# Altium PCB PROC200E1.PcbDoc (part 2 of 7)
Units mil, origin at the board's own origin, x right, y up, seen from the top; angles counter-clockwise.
Board outline 4163.97 x 3505.34 mil, 6 copper layers (Top Layer, GND1, SIG1, PWR, GND2, Bottom), stack 58.132 mil thick; 367 components, 387 nets, 1784 pads, 858 vias.
Unrouted connection lines stored in the file: 17.
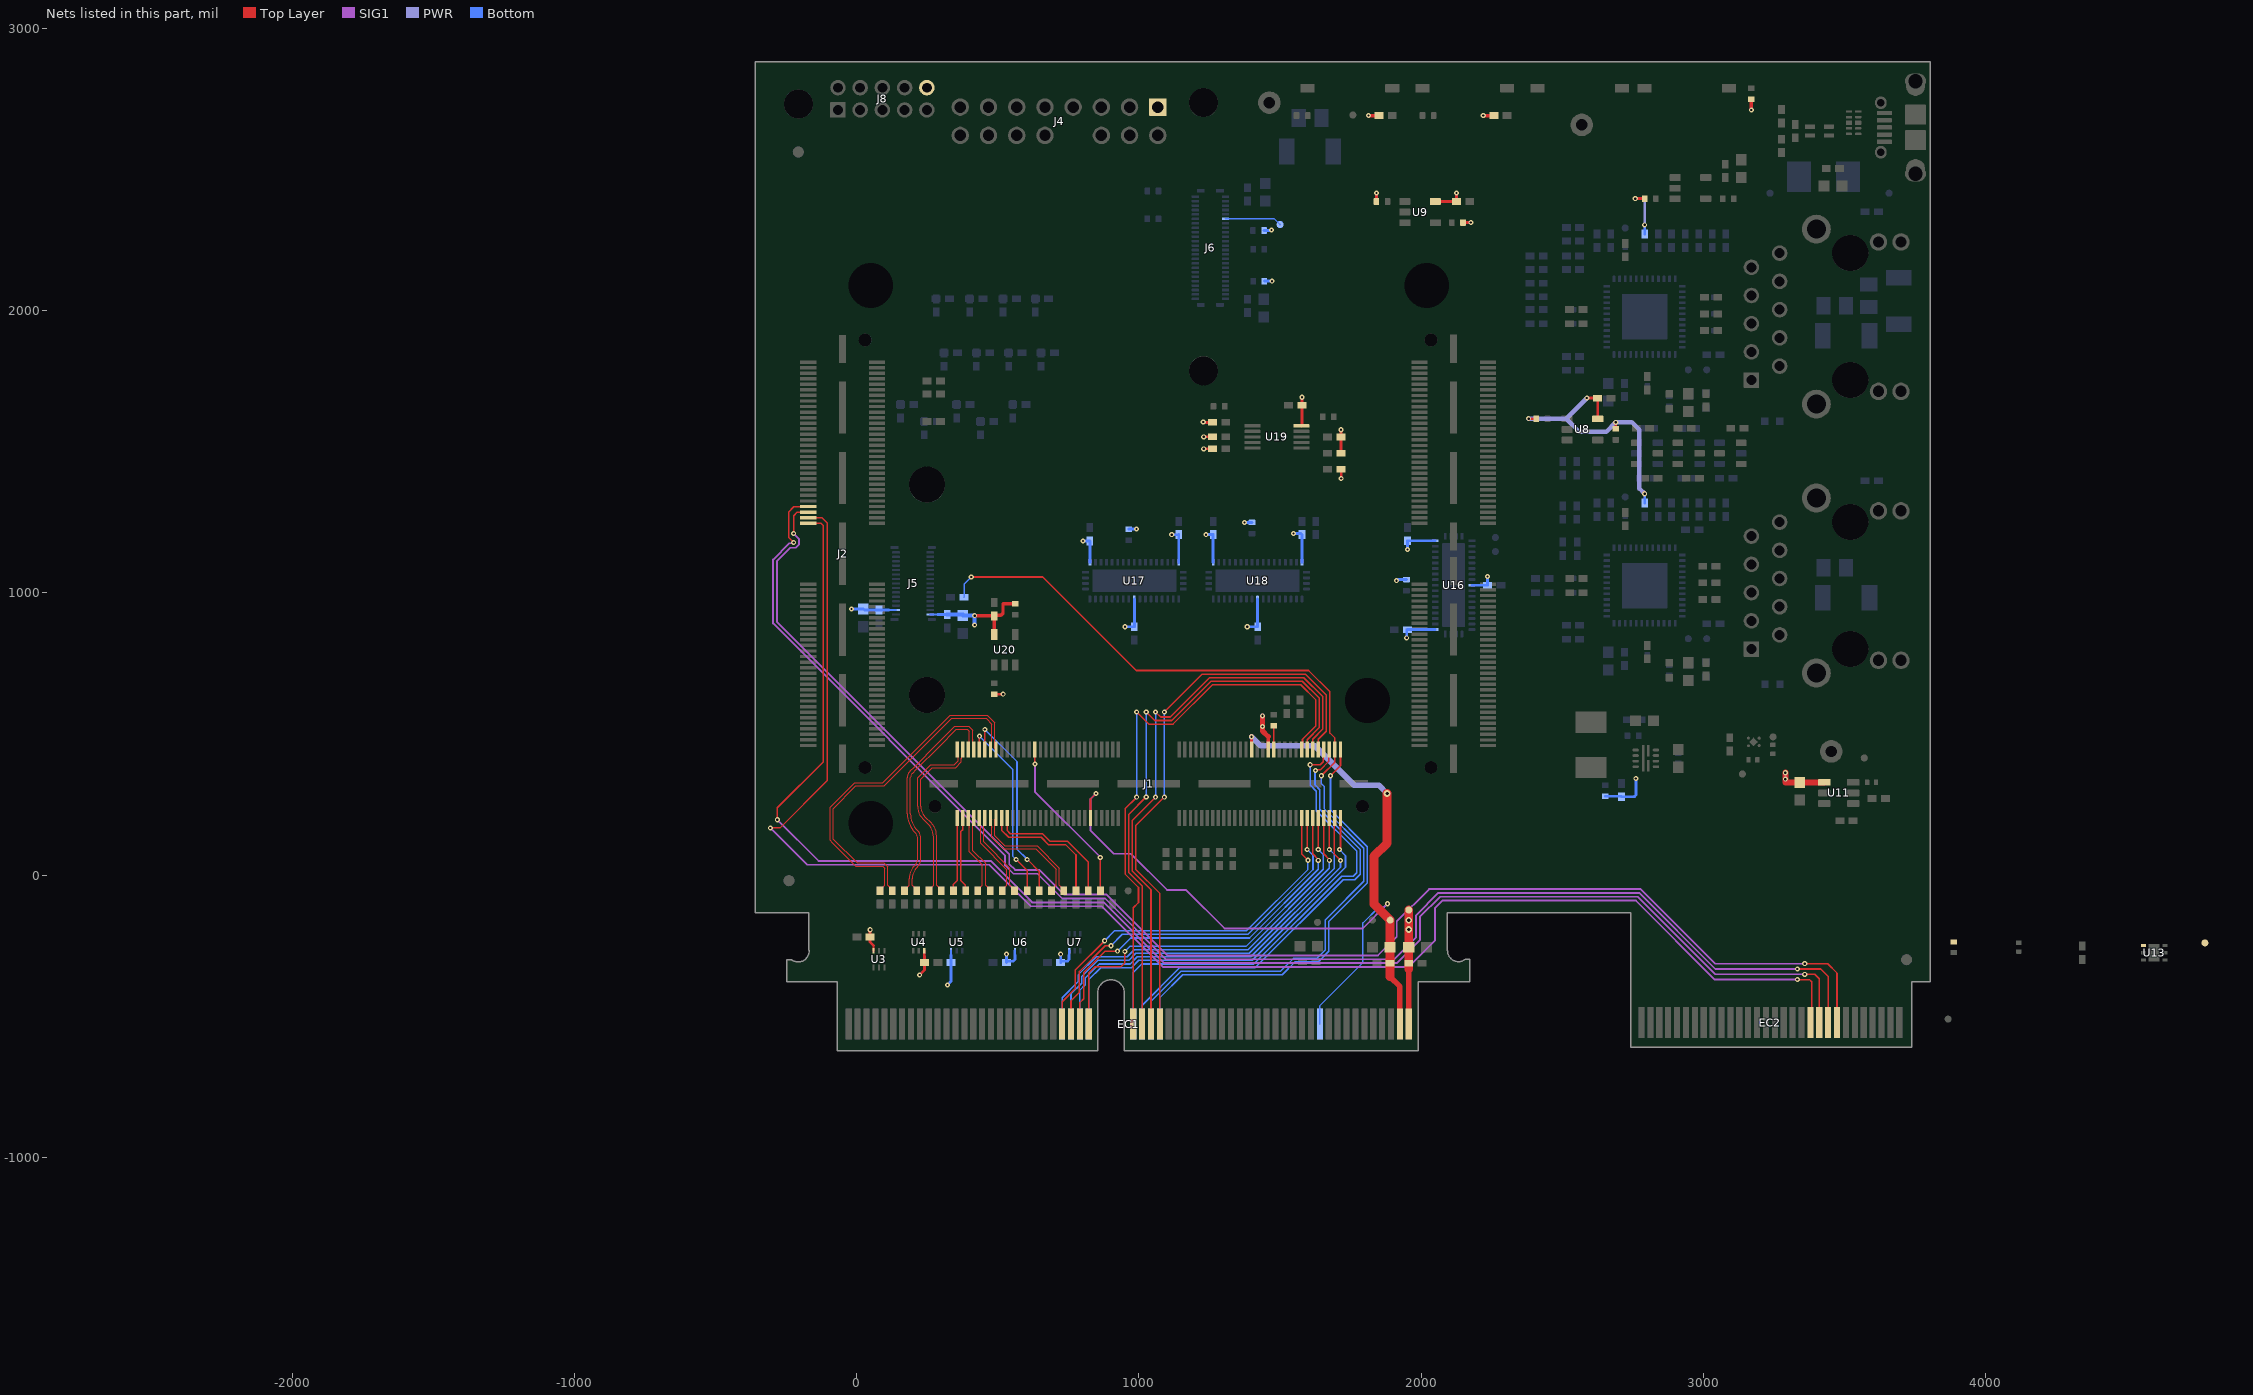
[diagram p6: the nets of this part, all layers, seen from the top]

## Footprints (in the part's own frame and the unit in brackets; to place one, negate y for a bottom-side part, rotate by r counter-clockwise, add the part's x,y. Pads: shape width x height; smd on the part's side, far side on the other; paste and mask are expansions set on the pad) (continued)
DBV0006A-MFG [mm]
  rrect17% 1.1x0.6 smd paste+0 mask+0: 1(-1.3,0.95) 2(-1.3,0) 3(-1.3,-0.95) 4(1.3,-0.95) 5(1.3,0) 6(1.3,0.95)
  silkscreen extent -2.52,-1.53 0.35,1.53, body extent -1.4,-1.45 1.4,1.45, height 1.45
DGS0010A-MFG [mm]
  rrect33% 1.45x0.3 smd paste+0 mask+0: 1(-2.2,1) 2(-2.2,0.5) 3(-2.2,0) 4(-2.2,-0.5) 5(-2.2,-1) 6(2.2,-1) 7(2.2,-0.5) 8(2.2,0) 9(2.2,0.5) 10(2.2,1)
  silkscreen extent -3.6,-1.55 1.05,1.55, body extent -3.03,-1.8 3.03,1.8, height 0.25
DPK0006A [mm] "SON, 6-Leads, Body 1.6x1.6mm, Pitch 0.5mm, TI Recommended"
  rect 0.5x0.2 smd paste+0: 1(-0.75,0.5) 2(-0.75,0) 3(-0.75,-0.5) 4(0.75,-0.5) 5(0.75,0) 6(0.75,0.5)
  Top Layer region: -0.65,0.5 -0.5,0.5 -0.5,0.7 -0.65,0.7
  silkscreen extent -0.97,-1 0.85,1, body extent -0.85,-0.85 0.85,0.85, height 0.61
DQA0010A [mm] "SON, 10-Leads, Body 1x2.5mm, Pitch 0.5mm, TI Recommended"
  rrect50% 0.565x0.2 smd: 1(-0.417,1) 2(-0.417,0.5) 4(-0.417,-0.5) 5(-0.417,-1) 6(0.417,-1) 7(0.417,-0.5) 9(0.417,0.5) 10(0.417,1)
  rrect28% 0.565x0.36 on Top Paste: 3(-0.417,0) 8(0.417,0)
  rrect25% 0.565x0.4 smd paste-0.2: 3(-0.417,0) 8(0.417,0)
  silkscreen extent -0.67,-1.45 0.55,1.45, body extent -0.55,-1.3 0.55,1.3, height 0.56
DQN0004A-MFG [mm]
  round 0.279 smd paste-1000 mask-1000: 1(-0.505,0.33) 2(-0.505,-0.33)
  round 0.251 smd paste-1000 mask-1000: 3(0.459,-0.346) 4(0.459,0.346)
  rrect17% 0.58x0.58 smd rot 135 paste-1000 mask-1000: 5(0,0)
  Top Layer region: -0.66,-0.485 -0.2,-0.485 -0.2,-0.385 -0.41,-0.175 -0.66,-0.175
  Top Layer region: 0.66,0.485 0.2,0.485 0.2,0.385 0.41,0.175 0.66,0.175
  Top Layer region: 0.66,-0.485 0.2,-0.485 0.2,-0.385 0.41,-0.175 0.66,-0.175
  Top Layer region: -0.66,0.485 -0.2,0.485 -0.2,0.385 -0.41,0.175 -0.66,0.175
  silkscreen extent -1.35,-0.9 0.53,0.9, body extent -0.5,-0.5 0.5,0.5, height 0.4
DRV0006A [mm] "SON, 6-Leads, Body 2x2mm, Pitch 0.65mm, Thermal Pad 1.6x1mm, TI Recommended"
  rrect33% 0.45x0.3 smd: 1(-0.975,0.65) 2(-0.975,0) 3(-0.975,-0.65) 4(0.975,-0.65) 5(0.975,0) 6(0.975,0.65)
  rrect14% 1x0.7 on Top Paste: 7(0,-0.45) 7(0,0.45)
  rrect10% 1x1.6 smd paste-0.5: 7(0,0)
  silkscreen extent -1.05,-1.2 1.05,1.2, body extent -1.05,-1.05 1.05,1.05, height 0.81
FCC_disclaimer [mil]
Fiducial10-20 [mm]
  round 1 smd mask+0.5: 1(0,0)
  Top Layer keep-out circle w1.178: c0,0 r0.5
FP-629105150921_CONN_PTH_USB_8MM0_5MM6-MFG [mm]
  rrect25% 0.4x1.35 smd paste+0 mask+0: 1(-1.3,2.335) 2(-0.65,2.335) 3(0,2.335) 4(0.65,2.335) 5(1.3,2.335)
  rrect100% 1.15x1.05 hole 0.65 slot 0.75 at 0 deg paste-2539.97 mask+0: 6(-2.225,2.65) 7(2.225,2.65)
  rrect100% 1.35x1.9 hole 1.3 slot 0.75 at 0 deg paste-2539.97 mask+0: 8(-4.175,-0.47) 11(4.173,-0.47)
  round 1.71 smd paste+0 mask+0: 8(-3.699,-0.47) 11(3.699,-0.47)
  rrect6% 1.8x1.9 smd paste+0 mask+0: 9(-1.15,-0.47) 10(1.15,-0.47)
  Top Layer region: 2.6,0.48 4.35,0.48 4.541,0.442 4.704,0.334 4.812,0.171 4.85,-0.02 4.85,-0.02 4.85,-0.92 4.812,-1.111 4.704,-1.274 4.541,-1.382 4.35,-1.42 4.35,-1.42 2.6,-1.42
  Top Layer region: -2.6,-1.42 -4.35,-1.42 -4.541,-1.382 -4.704,-1.274 -4.812,-1.111 -4.85,-0.92 -4.85,-0.92 -4.85,-0.02 -4.812,0.171 -4.704,0.334 -4.541,0.442 -4.35,0.48 -4.35,0.48 -2.6,0.48
  silkscreen extent -3.8,0.86 3.8,3.71, body extent -4.95,-2.7 4.95,3.27, height 0.25
FP-BLM18EG101TN1D_0603-MFG [mm]
  rrect15% 0.65x0.7 smd paste+0 mask+0: 1(-0.675,0) 2(0.675,0)
  silkscreen extent -0.87,-0.75 0.87,0.75, body extent -0.8,-0.4 0.8,0.4, height 0.65
FP-BSS138LT1G_SOT-23-3-MFG [mm]
  rrect18% 0.95x0.56 smd paste+0 mask+0: 1(-0.975,0.95) 2(-0.975,-0.95) 3(0.975,0)
  silkscreen extent -2.15,-1.52 0.7,1.52, body extent -1.2,-1.45 1.2,1.45, height 1.11
FP-DF40GB(1.5)-30DS-0.4V(58)_HDR30-MFG [mm]
  rrect50% 0.2x0.7 smd paste-1000 mask+0: 1(-2.8,-1.54) 2(-2.8,1.54) 3(-2.4,-1.54) 4(-2.4,1.54) 5(-2,-1.54) 6(-2,1.54) 7(-1.6,-1.54) 8(-1.6,1.54) 9(-1.2,-1.54) 10(-1.2,1.54) 11(-0.8,-1.54) 12(-0.8,1.54) 13(-0.4,-1.54) 14(-0.4,1.54) 15(0,-1.54) 16(0,1.54) 17(0.4,-1.54) 18(0.4,1.54) 19(0.8,-1.54) 20(0.8,1.54) 21(1.2,-1.54) 22(1.2,1.54) 23(1.6,-1.54) 24(1.6,1.54) 25(2,-1.54) 26(2,1.54) 27(2.4,-1.54) 28(2.4,1.54) 29(2.8,-1.54) 30(2.8,1.54)
  rrect36% 0.28x0.72 smd paste-1000 mask+0: 31(-3.24,1.68) 32(3.24,1.68) 33(-3.24,-1.68) 34(3.24,-1.68)
  silkscreen extent -4.47,-2.56 4.47,1.84, body extent -4.32,-1.84 4.32,1.84, height 1.6
FP-DF40GB-48DP-0.4V(58)_HDR48-MFG [mm]
  rrect43% 0.23x0.66 smd paste-1000 mask+0: 1(-4.6,-1.355) 2(-4.6,1.355) 3(-4.2,-1.355) 4(-4.2,1.355) 5(-3.8,-1.355) 6(-3.8,1.355) 7(-3.4,-1.355) 8(-3.4,1.355) 9(-3,-1.355) 10(-3,1.355) 11(-2.6,-1.355) 12(-2.6,1.355) 13(-2.2,-1.355) 14(-2.2,1.355) 15(-1.8,-1.355) 16(-1.8,1.355) 17(-1.4,-1.355) 18(-1.4,1.355) 19(-1,-1.355) 20(-1,1.355) 21(-0.6,-1.355) 22(-0.6,1.355) 23(-0.2,-1.355) 24(-0.2,1.355) 25(0.2,-1.355) 26(0.2,1.355) 27(0.6,-1.355) 28(0.6,1.355) 29(1,-1.355) 30(1,1.355) 31(1.4,-1.355) 32(1.4,1.355) 33(1.8,-1.355) 34(1.8,1.355) 35(2.2,-1.355) 36(2.2,1.355) 37(2.6,-1.355) 38(2.6,1.355) 39(3,-1.355) 40(3,1.355) 41(3.4,-1.355) 42(3.4,1.355) 43(3.8,-1.355) 44(3.8,1.355) 45(4.2,-1.355) 46(4.2,1.355) 47(4.6,-1.355) 48(4.6,1.355)
  rrect29% 0.35x0.7 smd paste-1000 mask+0: 49(-5.135,0.86) 50(5.135,0.86) 51(-5.135,-0.86) 52(5.135,-0.86)
  Top Layer keep-out region: 6.17,1.685 4.86,1.685 4.86,0.94 5.46,0.94 5.46,-0.94 4.86,-0.94 4.86,-1.685 6.17,-1.685
  Top Layer keep-out region: -6.17,1.685 -4.86,1.685 -4.86,0.94 -5.46,0.94 -5.46,-0.94 -4.86,-0.94 -4.86,-1.685 -6.17,-1.685
  silkscreen extent -5.53,-2.37 5.53,0.14, body extent -5.38,-1.49 5.38,1.49, height 1.29
FP-GRM155C81E105KE11D_0402-MFG [mm]
  rrect25% 0.4x0.5 smd paste+0 mask+0: 1(-0.4,0) 2(0.4,0)
  silkscreen extent -0.53,-0.65 0.53,0.65, body extent -0.5,-0.25 0.5,0.25, height 0.6
"FP-GRM155R61E225KE11D_0402 (1005 metric)-MFG" [mm]
  rrect22% 0.45x0.6 smd paste+0 mask+0: 1(-0.475,0) 2(0.475,0)
  silkscreen extent -0.6,-0.64 0.6,0.65, body extent -0.8,-0.45 0.8,0.45, height 0.25
FP-LPJG16314A4NL_CONN_RJ45-MFG [mm]
  rrect7% 1.4x1.4 hole 0.9 paste-2539.97 mask+0: 1(-5.715,9.015)
  round 1.4 hole 0.9 paste-2539.97 mask+0: 2(-4.445,6.475) 3(-3.175,9.015) 4(-1.905,6.475) 5(-0.635,9.015) 6(0.635,6.475) 7(1.905,9.015) 8(3.175,6.475) 9(4.445,9.015) 10(5.715,6.475)
  round 1.57 hole 1.02 paste-2539.97 mask+0: 11(6.725,-2.415) 12(6.725,-4.445) 13(-6.725,-2.415) 14(-6.725,-4.445)
  round 2.6 hole 1.7 paste-2539.97 mask+0: 15(-7.875,3.175) 16(7.875,3.175)
  round 3.25 hole 3.25 unplated paste-2539.97 mask+0: ""(-5.715,0.125) ""(5.715,0.125)
  silkscreen extent -9.65,-10.75 8.1,10.75, body extent -9.28,-10.85 9.28,10.85, height 0.25
FP-RC0402JR-0710KL_0402-MFG [mm]
  rrect20% 0.5x0.6 smd paste+0 mask+0: 1(-0.5,0) 2(0.5,0)
  silkscreen extent -0.5,-0.67 0.5,0.67, body extent -0.85,-0.4 0.85,0.4, height 0.25
FP-TDA01H0SB1R_SMT_SW_2MM40_6MM20-MFG [mm]
  rrect13% 1.27x0.76 smd paste+0 mask+0: 1(-3.81,0) 2(3.81,0)
  silkscreen extent -5.12,-1.2 3.1,1.2, body extent -4.54,-1.3 4.54,1.3, height 0.25
FP-TMM-105-01-T-D_HDR10-MFG [mm]
  rrect7% 1.39x1.39 hole 0.89 paste-2539.97 mask+0: 1(-4,-1)
  round 1.39 hole 0.89 paste-2539.97 mask+0: 2(-4,1) 3(-2,-1) 4(-2,1) 5(0,-1) 6(0,1) 7(2,-1) 8(2,1) 9(4,-1) 10(4,1)
  body extent -5,-1.97 5,1.97, height 4.88
FP-TSW-108-08-G-D-RA-008_HDR15-MFG [mm]
  rrect6% 1.57x1.57 hole 1.02 paste-2539.97 mask+0: 1(8.89,-2.77)
  round 1.57 hole 1.02 paste-2539.97 mask+0: 2(8.89,-5.31) 3(6.35,-2.77) 4(6.35,-5.31) 5(3.81,-2.77) 6(3.81,-5.31) 7(1.27,-2.77) 9(-1.27,-2.77) 10(-1.27,-5.31) 11(-3.81,-2.77) 12(-3.81,-5.31) 13(-6.35,-2.77) 14(-6.35,-5.31) 15(-8.89,-2.77) 16(-8.89,-5.31)
  silkscreen extent -10.35,-2.89 10.35,1.34, body extent -10.16,-5.65 10.16,7.11, height 5.69
IHLP-2020BZ [mm] "Vishay Dale recommended land pattern.  Document 34261 rev 12-Sept-13"
  rect 1.915x2.79 smd: 1(-2.037,0) 2(2.037,0)
  silkscreen extent -2.9,-2.7 2.9,2.7, body extent -2.87,-2.72 2.87,2.72, height 2
IND_DLW21S [mm] "muRata"
  rrect25% 0.4x0.9 smd: 1(-0.4,0.85) 2(-0.4,-0.85) 3(0.4,-0.85) 4(0.4,0.85)
  silkscreen extent -1.23,0.66 -0.98,0.92, body extent -0.6,-1 0.6,1, height 1.21
Keystone5002 [mil] "For Keystone 500x miniature loop terminals"
  round 80 hole 40: 1(0,0)
  silkscreen extent -52,-52 52,52, body extent -49,-49 49,49, height 182
Label_650x200 [mil] "Thermal Transfer Label"
  round 1 on Mech13: 0(0,0)
  silkscreen extent -325,-100 325,100, body extent -325,-100 325,100, height 1
MTG_159mil [mil] "159mil Non Plated Hole"
  round 150 hole 159 unplated: 1(0,0)
RGZ0048B-MFG [mm]
  rrect42% 0.6x0.24 smd paste+0 mask+0: 1(-3.4,2.75) 2(-3.4,2.25) 3(-3.4,1.75) 4(-3.4,1.25) 5(-3.4,0.75) 6(-3.4,0.25) 7(-3.4,-0.25) 8(-3.4,-0.75) 9(-3.4,-1.25) 10(-3.4,-1.75) 11(-3.4,-2.25) 12(-3.4,-2.75) 25(3.4,-2.75) 26(3.4,-2.25) 27(3.4,-1.75) 28(3.4,-1.25) 29(3.4,-0.75) 30(3.4,-0.25) 31(3.4,0.25) 32(3.4,0.75) 33(3.4,1.25) 34(3.4,1.75) 35(3.4,2.25) 36(3.4,2.75)
  rrect42% 0.24x0.6 smd paste+0 mask+0: 13(-2.75,-3.4) 14(-2.25,-3.4) 15(-1.75,-3.4) 16(-1.25,-3.4) 17(-0.75,-3.4) 18(-0.25,-3.4) 19(0.25,-3.4) 20(0.75,-3.4) 21(1.25,-3.4) 22(1.75,-3.4) 23(2.25,-3.4) 24(2.75,-3.4) 37(2.75,3.4) 38(2.25,3.4) 39(1.75,3.4) 40(1.25,3.4) 41(0.75,3.4) 42(0.25,3.4) 43(-0.25,3.4) 44(-0.75,3.4) 45(-1.25,3.4) 46(-1.75,3.4) 47(-2.25,3.4) 48(-2.75,3.4)
  rrect2% 4.1x4.1 smd paste-1000 mask+0: 49(0,0)
  silkscreen extent -4.38,-3.57 3.57,3.57, body extent -3.5,-3.5 3.5,3.5, height 1.02
RUA0042A-MFG [mm]
  rrect40% 0.6x0.25 smd paste+0 mask+0: 1(-1.65,4) 2(-1.65,3.5) 3(-1.65,3) 4(-1.65,2.5) 5(-1.65,2) 6(-1.65,1.5) 7(-1.65,1) 8(-1.65,0.5) 9(-1.65,0) 10(-1.65,-0.5) 11(-1.65,-1) 12(-1.65,-1.5) 13(-1.65,-2) 14(-1.65,-2.5) 15(-1.65,-3) 16(-1.65,-3.5) 17(-1.65,-4) 22(1.65,-4) 23(1.65,-3.5) 24(1.65,-3) 25(1.65,-2.5) 26(1.65,-2) 27(1.65,-1.5) 28(1.65,-1) 29(1.65,-0.5) 30(1.65,0) 31(1.65,0.5) 32(1.65,1) 33(1.65,1.5) 34(1.65,2) 35(1.65,2.5) 36(1.65,3) 37(1.65,3.5) 38(1.65,4)
  rrect40% 0.25x0.6 smd paste+0 mask+0: 18(-0.75,-4.4) 19(-0.25,-4.4) 20(0.25,-4.4) 21(0.75,-4.4) 39(0.75,4.4) 40(0.25,4.4) 41(-0.25,4.4) 42(-0.75,4.4)
  rrect5% 2.05x7.55 smd paste-1000 mask+0: 43(0,0)
  silkscreen extent -2.65,-4.55 1.8,4.55, body extent -1.75,-4.5 1.75,4.5, height 0.8
RWK0011B [mm] "QFN, 11-Leads, Body 2.1x2.1mm, Pitch 0.5mm, TI Recommended"
  rect 1.05x0.2 smd paste-0.1: 1(-0.675,0.225) 7(0.675,0.225)
  rect 2.4x0.2 smd paste-0.1: 2(0,-0.225)
  oval 0.25x0.575 smd: 3(-0.75,-0.913) 4(-0.25,-0.913) 5(0.25,-0.913) 6(0.75,-0.913) 8(0.75,0.913) 9(0.25,0.913) 10(-0.25,0.913) 11(-0.75,0.913)
  silkscreen extent -1.2,-0.93 1.2,1.1, body extent -1.05,-1.05 1.05,1.05, height 1.01
SAMTEC_QTH-060-01-L-D-A [mm] "SMD, 60x2 Position, Body 40.01x5.97mm"
  rect 0.305x1.45 smd: 1(-17.25,3.086) 2(-17.25,-3.086) 3(-16.75,3.086) 4(-16.75,-3.086) 5(-16.25,3.086) 6(-16.25,-3.086) 7(-15.75,3.086) 8(-15.75,-3.086) 9(-15.25,3.086) 10(-15.25,-3.086) 11(-14.75,3.086) 12(-14.75,-3.086) 13(-14.25,3.086) 14(-14.25,-3.086) 15(-13.75,3.086) 16(-13.75,-3.086) 17(-13.25,3.086) 18(-13.25,-3.086) 19(-12.75,3.086) 20(-12.75,-3.086) 21(-12.25,3.086) 22(-12.25,-3.086) 23(-11.75,3.086) 24(-11.75,-3.086) 25(-11.25,3.086) 26(-11.25,-3.086) 27(-10.75,3.086) 28(-10.75,-3.086) 29(-10.25,3.086) 30(-10.25,-3.086) 31(-9.75,3.086) 32(-9.75,-3.086) 33(-9.25,3.086) 34(-9.25,-3.086) 35(-8.75,3.086) 36(-8.75,-3.086) 37(-8.25,3.086) 38(-8.25,-3.086) 39(-7.75,3.086) 40(-7.75,-3.086) 41(-7.25,3.086) 42(-7.25,-3.086) 43(-6.75,3.086) 44(-6.75,-3.086) 45(-6.25,3.086) 46(-6.25,-3.086) 47(-5.75,3.086) 48(-5.75,-3.086) 49(-5.25,3.086) 50(-5.25,-3.086) 51(-4.75,3.086) 52(-4.75,-3.086) 53(-4.25,3.086) 54(-4.25,-3.086) 55(-3.75,3.086) 56(-3.75,-3.086) 57(-3.25,3.086) 58(-3.25,-3.086) 59(-2.75,3.086) 60(-2.75,-3.086) 61(2.75,3.086) 62(2.75,-3.086) 63(3.25,3.086) 64(3.25,-3.086) 65(3.75,3.086) 66(3.75,-3.086) 67(4.25,3.086) 68(4.25,-3.086) 69(4.75,3.086) 70(4.75,-3.086) 71(5.25,3.086) 72(5.25,-3.086) 73(5.75,3.086) 74(5.75,-3.086) 75(6.25,3.086) 76(6.25,-3.086) 77(6.75,3.086) 78(6.75,-3.086) 79(7.25,3.086) 80(7.25,-3.086) 81(7.75,3.086) 82(7.75,-3.086) 83(8.25,3.086) 84(8.25,-3.086) 85(8.75,3.086) 86(8.75,-3.086) 87(9.25,3.086) 88(9.25,-3.086) 89(9.75,3.086) 90(9.75,-3.086) 91(10.25,3.086) 92(10.25,-3.086) 93(10.75,3.086) 94(10.75,-3.086) 95(11.25,3.086) 96(11.25,-3.086) 97(11.75,3.086) 98(11.75,-3.086) 99(12.25,3.086) 100(12.25,-3.086) 101(12.75,3.086) 102(12.75,-3.086) 103(13.25,3.086) 104(13.25,-3.086) 105(13.75,3.086) 106(13.75,-3.086) 107(14.25,3.086) 108(14.25,-3.086) 109(14.75,3.086) 110(14.75,-3.086) 111(15.25,3.086) 112(15.25,-3.086) 113(15.75,3.086) 114(15.75,-3.086) 115(16.25,3.086) 116(16.25,-3.086) 117(16.75,3.086) 118(16.75,-3.086) 119(17.25,3.086) 120(17.25,-3.086)
  rect 2.54x0.64 smd: A1(-18.44,0) A4(-1.55,0) A5(1.56,0) A8(18.45,0)
  rect 4.7x0.64 smd: A2(-13.17,0) A3(-6.82,0) A6(6.83,0) A7(13.18,0)
  round 1.15 hole 1.15 unplated mask+0: MH1(-19.24,2.03) MH2(19.24,2.03)
  silkscreen extent -20,-2.99 20,2.99, body extent -20.07,-3.56 19.94,3.56, height 4.32
SMB-Bi [mil] "Molded Diode, 2-Leads, Body 5.4x3.6mm, IPC Medium Density, based on OnSemi component dimensions"
  rect 85x107.99 smd: 1(-87.01,0) 2(87.01,0)
  silkscreen extent -125,-79 125,79, body extent -104,-73 104,73, height 89
TI_Stacked_Overlay_Small [mil]
  silkscreen extent -418,-98 418,98
TP_25MIL-SMT [mil]
  round 25 smd mask-2.5: 1(0,0)
WEEE_Minimum [mil] "WEEElie bin"
  silkscreen extent -95,-172 99,104

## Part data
C1 C9 C15 C21 C23 C25 C27 C29 C31 C45 C51 C57 C59 C72 C74 C102 C104: library part CMP-0086062-1, "CAP, CERM, 10 µF, 16 V,+/- 20%, X6S, 0603", Cap_Case=0603, Manufacturer=MuRata, TempCo=X6S, Tolerance_%=20%, Value2=16V, ValueDisplayed=10µF
C2 C10 C16 C38 C46 C52 C75 C77 C88: library part CMP-0006352-2, "CAP, CERM, 0.01 uF, 25 V, +/- 10%, X7R, 0402", Cap_Case=0402, Manufacturer=MuRata, Supplier Part Number 1=490-6043-2-ND, TempCo=X7R, Tolerance_%=10%, Value1=Unknown, Value2=25V, ValueDisplayed=0.01uF
C3 C5 C7 C12 C14 C18 C20 C22 C24 C26 C28 C30 C32 C33 C34 C35 C36 C37 C39 C41 C43 C48 C50 C54 C56 C58 C60 C71 C103 C105 C109 C110 C111 C112 C113 C114 C115 C116 C117 C118 C121: library part CMP-0006659-2, "CAP, CERM, 0.1 uF, 25 V, +/- 10%, X7R, 0402", Cap_Case=0402, Manufacturer=MuRata, Supplier Part Number 1=490-10698-1-ND, TempCo=X7R, Tolerance_%=10%, Value1=Unknown, Value2=25V, ValueDisplayed=0.1uF
C4 C6 C8 C11 C13 C17 C19 C40 C42 C44 C47 C49 C53 C55 C76 C78 C97 C100: library part CMP-0121658-2, "Chip Multilayer Ceramic Capacitors for General Purpose, 0402, 1.0uF, X6S, 22%, 10%, 25V", Manufacturer=Murata, Operating Temperature Range="-55°C to +105°C", TempCo=22%, Temperature Characteristic=X6S, Tolerance_%=10%, ValueDisplayed=1.0uF
C61 C108 C119 C120: library part CMP-0009436-2, "CAP, CERM, 1000 pF, 2000 V, +/- 10%, X7R, 1808", Cap_Case=1808, Manufacturer=MuRata, Supplier Part Number 1=490-8145-1-ND, TempCo=X7R, Tolerance_%=10%, Value1=Unknown, Value2=2000V, ValueDisplayed=1000pF
C62 C63 C64 C65 C66 C67 C68 C69 C70 C79 C80 C81 C82 C83 C84 C85 C86 C87 C94: library part CMP-0006456-2, "CAP, CERM, 330 pF, 50 V, +/- 5%, C0G/NP0, 0402", Cap_Case=0402, Manufacturer=MuRata, Supplier Part Number 1=490-1295-1-ND, TempCo=C0G/NP0, Tolerance_%=5%, Value1=Unknown, Value2=50V, ValueDisplayed=330pF
C73: library part CMP-0007306-5, "CAP, CERM, 22 uF, 6.3 V, +/- 20%, X5R, 0603", Cap_Case=0603, Manufacturer=MuRata, Supplier Part Number 1=490-7611-1-ND, TempCo=X5R, Tolerance_%=20%, Value1=Unknown, Value2=6.3V, ValueDisplayed=22uF
C89: library part CMP-0089929-1, "2.2µF ±10% 25V Ceramic Capacitor X5R 0402 (1005 Metric)", Digikey Part Number=490-12703-1-ND, Manufacturer=Murata, Mouser Part Number=81-GRM155R61E225KE1D, Operating Temperature Range="-55°C to +85°C", TempCo=15%, Temperature Characteristic=X5R, Tolerance_%=10%, ValueDisplayed=2.2uF, Voltage=25V
D1: library part CMP-0005599-2, "Diode, TVS, Bi, 6.5 V, SMB", Manufacturer=Littelfuse, Value1=600W
EC1: library part CMP-0003813-3, "C2000 controlCARD-120HSEC Edge Connector for Samtec HSEC8-160-01-L-DV-A-BL", Manufacturer=Any
EC2: library part CMP-0081961-1, "C2000 controlCARD-180HSEC (60-pin addon) Edge connector for Samtec HSEC8-130-01-L-DV-A", Manufacturer=Any
FB1 FB2 FB3 FB4 FB5 FB6: library part CMP-0122093-1, "Chip Ferrite Bead, 0603, 100Ω @ 100MHz, 25%, 0.045Ω, 2A", Impedance At Frequency="100Ω @ 100MHz", Manufacturer=Murata, Operating Temperature Range="-55°C to +125℃", Test Frequency=100MHz, Tolerance_%=25%
FID1 FID2 FID3 FID4 FID5 FID6: library part CMP-0077181-1, "Fiducial mark.  There is nothing to buy or mount.", Manufacturer=N/A
J1 J2 J3: library part CMP-0056023-2, "Socket, 0.5MM, 60x2, Gold, SMT", Manufacturer=Samtec, Supplier Part Number 1=SAM8189-ND
J4: library part CMP-0121702-1, "Connector Header Through Hole, Right Angle 16 position 0.100\" (2.54mm)", Digikey Part Number=612-TSW-108-08-G-D-RA-008-ND, Manufacturer=Samtec, Mouser Part Number=200-TSW10808GDRA008, Operating Temperature Range="-55°C to +125°C"
J5: library part CMP-0121593-1, "30 Position Connector Receptacle, Center Strip Contacts Surface Mount Gold", Current_A=300mA, Digikey Part Number=H124958CT-ND, Manufacturer=Hirose, Mouser Part Number=798-DF40GB1530DS4V58, Operating Temperature Range="-55°C to +85°C", Voltage_V=50V
J6: library part CMP-0121592-1, "48 Position Connector Plug, Outer Shroud Contacts Surface Mount Gold", Current_A=300mA, Digikey Part Number=H124956CT-ND, Manufacturer=Hirose, Mouser Part Number=798-DF40GB48DP04V58, Operating Temperature Range="-55°C to +85°C", Voltage_V=50V
J7: library part CMP-0097752-1, "Conn Micro USB 2.0 Type AB RCP 5 POS 0.65mm Solder RA SMD 5 Terminal 1 Port T/R", Current_A=1A, Digikey Part Number=732-5961-1-ND, Manufacturer="Wurth Electronics", Mouser Part Number=710-629105150921, Operating Temperature Range="-40°C to +85°C", Voltage_V=30V
J8: library part CMP-0086568-1, "Board-To-Board Connector, TMM Series, 10 Contacts, Header, 2 mm, Through Hole, 2 Rows", Current_A=3.2A, Manufacturer=Samtec, Voltage_V=281V
J9 J10: library part CMP-0093483-1, "RJ45 Connector with 1000 Base-TX Inetgrated Magnetic", Manufacturer=Link-PP, Operating Temperature Range="0°C to +70°C"
L1: library part CMP-0076826-3, "Coupled inductor, 0.28 A, 0.41 ohm, SMD", Manufacturer=MuRata, Supplier Part Number 1=490-5134-1-ND
L2: library part CMP-0063289-1, "Inductor, Shielded Drum Core, Powdered Iron, 1 uH, 7 A, 0.0189 ohm, SMD", Manufacturer=Vishay-Dale, Supplier Part Number 1=541-1087-1-ND, Value1="0.0189 ohm", Value2=7A, ValueDisplayed=1uH
LBL1: library part CMP-0003625-1, "Thermal Transfer Printable Labels, 0.650\" W x 0.200\" H - 10,000 per roll", Manufacturer=Brady, Supplier Part Number 1=97C5133
Logo1: library part CMP-0074844-1
Logo2: library part CMP-0074838-1, "Texas Instrument Corporate Signature"
Logo3: library part CMP-0074847-1, "FCC_disclaimer"
Logo4: library part CMP-0074769-3, Manufacturer="Texas Instruments"
MH1 MH2 MH3 MH4: library part CMP-0078424-2, "PCB Mounting Hole, No Pad", Manufacturer=Any, PartNumber=N/A
Q1 Q2 Q3 Q4 Q5 Q6: library part CMP-0122033-1, "N-Channel 50 V 200mA (Ta) 225mW (Ta) Surface Mount SOT-23-3 (TO-236)D3-3", Digikey Part Number=BSS138LT1GOSCT-ND, Drain To Source Breakdown Voltage=50V, Input Capacitace At Vds="40pF @ 25V", Manufacturer="On Semiconductor", Mouser Part Number=863-BSS138LT1G, Operating Temperature Range="-55°C to +150°C", Power_W=225mW, Pulse Drain Current=800mA
R1 R3 R4 R24 R25 R26 R27 R28 R29 R30 R31 R32 R33 R34 R35 R36 R37 R38 R39 R40 R41 R45 R46 R47 R48 R49 R50 R51 R52 R53 R54 R55 R56 R57 R59 R85 R87 R90 R92 R93 R109 R111 R113 R116 R119 R120 R125 R126 R127 R132 R134 R135 R136 R137 R138 R139 R140 R141 R142 R143 R144 R145 R146 R147 R148 R149 R150 R151 R152 R153 R156 R157 R158 R159 R160 R161 R162: library part CMP-0026992-3, "RES, 0, 5%, 0.1 W, AEC-Q200 Grade 0, 0402", Manufacturer=Panasonic, Power_W=100mW, Supplier Part Number 1=P0.0JCT-ND, TempCo="600 ppm/C", Tolerance_%=5%, Value2=0.1W, Value_Code=0000, ValueDisplayed=0
R2 R58 R155: library part CMP-0025975-3, "RES, 11.0 k, 1%, 0.063 W, AEC-Q200 Grade 0, 0402", Manufacturer=Vishay-Dale, Power_W=63mW, Supplier Part Number 1=541-11.0KLCT-ND, TempCo="100 ppm/C", Tolerance_%=1%, Value2=0.063W, Value_Code=11k0, ValueDisplayed=11.0k
R5 R60 R100 R101 R102 R103 R104 R105: library part CMP-0026231-2, "RES, 2.20 k, 1%, 0.063 W, AEC-Q200 Grade 0, 0402", Manufacturer=Vishay-Dale, Power_W=63mW, Supplier Part Number 1=541-2.20KLCT-ND, TempCo="100 ppm/C", Tolerance_%=1%, Value2=0.063W, Value_Code=2k20, ValueDisplayed=2.20k
R6 R7 R8 R9 R10 R11 R12 R13 R14 R15 R16 R17 R18 R19 R20 R21 R22 R23 R61 R62 R63 R64 R65 R66 R67 R68 R69 R70 R71 R72 R73 R74 R75 R76 R77 R78: library part CMP-0026237-2, "RES, 2.49 k, 1%, 0.063 W, AEC-Q200 Grade 0, 0402", Manufacturer=Vishay-Dale, Power_W=63mW, Supplier Part Number 1=541-2.49KLCT-ND, TempCo="100 ppm/C", Tolerance_%=1%, Value2=0.063W, Value_Code=2k49, ValueDisplayed=2.49k
R42 R43 R44 R79 R80 R81 R82 R83 R86 R88 R89 R91 R95 R96 R97 R98 R99 R106 R107 R122 R123 R124 R128 R133: library part CMP-0094798-1, "Res Thick Film 0402 10K Ohm 5% 0.063W(1/16W) ±100ppm/C Pad SMD T/R", Digikey Part Number=311-10KJRCT-ND, Manufacturer=YAGEO, Mouser Part Number=603-RC0402JR-0710KL, Operating Temperature Range="-55°C to +155°C", Power_W=63mW, TempCo=100ppm/°C, Tolerance_%=5%
R84 R94 R114 R121: library part CMP-0020616-3, "RES, 0, 5%, 0.125 W, AEC-Q200 Grade 0, 0805", Manufacturer=Panasonic, Power_W=125mW, Supplier Part Number 1=P0.0ACT-ND, TempCo="600 ppm/C", Tolerance_%=5%, Value2=0.125W, Value_Code=0000, ValueDisplayed=0
R108 R110 R112 R115 R117 R118: library part CMP-0026878-3, "RES, 220, 5%, 0.063 W, AEC-Q200 Grade 0, 0402", Manufacturer=Vishay-Dale, Power_W=63mW, Supplier Part Number 1=541-220JCT-ND, TempCo="200 ppm/C", Tolerance_%=5%, Value2=0.063W, Value_Code=220R, ValueDisplayed=220
R129: library part CMP-0026938-5, "RES, 4.7 k, 5%, 0.063 W, AEC-Q200 Grade 0, 0402", Manufacturer=Vishay-Dale, Power_W=63mW, Supplier Part Number 1=541-4.7KJCT-ND, TempCo="200 ppm/C", Tolerance_%=5%, Value2=0.063W, Value_Code=4k70, ValueDisplayed=4.7k
R130 R131: library part CMP-0026657-1, "RES, 1.00 k, 1%, 0.1 W, 0402", Manufacturer=Panasonic, Power_W=100mW, Supplier Part Number 1=P1.00KLCT-ND, TempCo="100 ppm/C", Tolerance_%=1%, Value2=0.1W, Value_Code=1k00, ValueDisplayed=1.00k
R154: library part CMP-0026989-6, "RES, 9.1 k, 5%, 0.063 W, AEC-Q200 Grade 0, 0402", Manufacturer=Vishay-Dale, Power_W=63mW, Supplier Part Number 1=541-9.1KJCT-ND, TempCo="200 ppm/C", Tolerance_%=5%, Value2=0.063W, Value_Code=9k10, ValueDisplayed=9.1k
SW1 SW2 SW3 SW4: library part CMP-0122841-1, "Dip Switch SPST 1 Position Surface Mount Slide (Standard) Actuator 25mA 24VDC", Coil Resistance_ohm=100mΩ, Contact Current Rating=25mA, Digikey Part Number=CKN10538CT-ND, Manufacturer="C&K Components", Mouser Part Number=611-TDA01H0SB1R, Operating Temperature Range="-40°C to +85°C"
TP1 TP2 TP3 TP4 TP18 TP25: "TEST POINT.  No entry in BOM.", Manufacturer=N/A
TP5 TP6 TP7 TP8 TP9 TP10 TP11 TP12 TP13 TP14 TP15 TP16 TP17 TP20 TP21 TP24: library part CMP-0078143-3, "TEST POINT.  No entry in BOM.", Manufacturer=N/A
TP19 TP22 TP23: library part CMP-0055139-2, "Test Point, Miniature, White, TH", Color=White, Manufacturer="Keystone Electronics", Supplier Part Number 1=36-5002-ND
U1 U2: library part CMP-0091377-1, "1/1 Transceiver Ethernet 48-VQFN (7x7)", Digikey Part Number=296-53377-1-ND, Manufacturer="Texas Instruments", Max Supply Voltage=3.45V, Min Supply Voltage=990mV, Mouser Part Number=595-DP83869HMRGZT, Operating Temperature Range="-40°C to +125°C"
U3 U4 U5 U6 U7: library part CMP-0043110-1, "Low-Capacitance + / - 15-kV ESD Protection Array for High-Speed Data Interfaces, 4 Channels, -40 to +85 degC, 6-pin USON (DPK), Green (RoHS & no Sb/Br)", Breakdown Voltage(Min)(V)=11, IO Capacitance(Typ)(pF)=1.5, Manufacturer="Texas Instruments"
U8 U9 U20: library part CMP-0051264-2, "Single 2-Input Positive–AND Gate with Open Drain Output,  DBV0005A (SOT-23-5)", F @ Nom Voltage(Max)(Mhz)=75, Generic Part Number=SN74AHC1G09, ICC @ Nom Voltage(Max)(mA)=0.01, Manufacturer="Texas Instruments", Operating Temperature Range="-55 to 125 C", Rating=Catalog, tpd @ Nom Voltage(Max)(ns)=11,7.5, Voltage(Nom)(V)=3.3,5
U10: library part CMP-0074023-2, "2-A Step Down Converter with Selectable Switching Frequency in HotRod package, RWK0011B (VQFN-HR-11)", Alternate Manufacturer="Texas Instruments", Alternate PartNumber=TPS62097RWKT
U11: library part CMP-0122847-1, "5.5-V, 2-A, 52-mΩ load switch with adj. rise time and adj. output discharge", Digikey Part Number=296-46278-1-ND, Manufacturer="Texas Instruments", Max Supply Voltage=5.5V, Mouser Part Number=595-TPS22918DBVR, Nominal Supply Current=8.3-10.2uA, Operating Temperature Range="-40°C to +105°C"
U12: library part CMP-0122846-1, "LDO Regulator Pos 1.1V 0.5A 4-Pin X2SON EP T/R", Digikey Part Number=296-51784-1-ND, Dropout Voltage=550mV, Manufacturer="Texas Instruments", Max Supply Voltage=5.5V, Min Supply Voltage=2V, Mouser Part Number=595-TLV75511PDQNR, Nominal Supply Current=25uA, Operating Temperature Range="-40°C to +125°C", Output Voltage=1.1V
U13: library part CMP-0036330-5, "Single Output High PSRR LDO, 500 mA, Fixed 3.3 V Output, 2.7 to 6.5 V Input, with Low IQ, 6-pin SON (DRV), -40 to 125 degC, Green (RoHS & no Sb/Br)", Manufacturer="Texas Instruments"
U14: library part CMP-0074276-1, "Single, Current-Limited, Power-Distribution Switch, DBV0005A (SOT-23-5)", Alternate Manufacturer="Texas Instruments", Alternate PartNumber=TPS2051BDBVT
U15: library part CMP-0073612-3, "4-Channel ESD Protection Diode for USB Type-C and HDMI 2.0, DQA0010A (USON-10)", Alternate Manufacturer="Texas Instruments"
U16 U17 U18: library part CMP-0093539-2, "IC MUX/DEMUX DDR3 1:2 42WQFN", Digikey Part Number=296-28307-1-ND, Manufacturer="Texas Instruments", Max Supply Voltage=3.6V, Min Supply Voltage=3V, Mouser Part Number=595-TS3DDR3812RUAR, Nominal Supply Current=300uA, On State Resistance=8Ω, Operating Temperature Range="-40°C to +85°C"
U19: library part CMP-0122044-1, "ESD-Protected, Low Capacitance, 2-Channel, 2:1 Switch, With Powered-off Protection", Digikey Part Number=296-48347-1-ND, Manufacturer="Texas Instruments", Max Supply Voltage=4.3V, Min Supply Voltage=3V, Mouser Part Number=595-TMUX154EDGSR, Nominal Supply Current=1uA, On State Resistance=6Ω, Operating Temperature Range="-40°C to +85°C"
ZZ1: library part CMP-0003616-3
ZZ2: library part CMP-0077236-1
ZZ3: library part CMP-0077237-1
ZZ4: library part CMP-0077238-1

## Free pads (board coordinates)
  round 1.38 on Mech4: 1(-2738.83,-78.63) 1(-2738.83,-78.63) 1(-2738.83,-68.78) 1(-2738.83,-21.54) 1(-2738.83,-11.7) 1(-2738.83,-11.7) 1(-2703.39,-78.63) 1(-2703.39,-78.63) 1(-2703.39,-68.78) 1(-2703.39,-21.54) 1(-2703.39,-11.7) 1(-2703.39,-11.7) 1(-2602,-78.63) 1(-2602,-78.63) 1(-2602,-68.78) 1(-2602,-21.54) 1(-2602,-11.7) 1(-2602,-11.7) 1(-2566.56,-78.63) 1(-2566.56,-78.63) 1(-2566.56,-68.78) 1(-2566.56,-21.54) 1(-2566.56,-11.7) 1(-2566.56,-11.7) 1(-1656.99,1356.81) 1(-1656.99,1356.81) 1(-1656.99,1392.24) 1(-1656.99,1392.24) 1(-1647.14,1356.81) 1(-1647.14,1392.24) 1(-1599.9,1356.81) 1(-1599.9,1392.24) 1(-1590.06,1356.81) 1(-1590.06,1356.81) 1(-1590.06,1392.24) 1(-1590.06,1392.24) 1(-1532.26,-29.39) 1(-1532.26,-29.39) 1(-1532.26,6.04) 1(-1532.26,6.04) 1(-1531.74,-141.35) 1(-1531.74,-141.35) 1(-1531.74,-105.92) 1(-1531.74,-105.92) 1(-1522.41,-29.39) 1(-1522.41,6.04) 1(-1521.9,-141.35) 1(-1521.9,-105.92) 1(-1475.17,-29.39) 1(-1475.17,6.04) 1(-1474.65,-105.92) 1(-1474.65,-141.35) 1(-1465.33,-29.39) 1(-1465.33,-29.39) 1(-1465.33,6.04) 1(-1465.33,6.04) 1(-1464.81,-105.92) 1(-1464.81,-105.92) 1(-1464.81,-141.35) 1(-1464.81,-141.35) 1(-1416.07,1313.15) 1(-1416.07,1313.15) 1(-1416.07,1348.59) 1(-1416.07,1348.59) 1(-1406.23,1313.15) 1(-1406.23,1348.59) 1(-1358.98,1313.15) 1(-1358.98,1348.59) 1(-1349.14,1313.15) 1(-1349.14,1313.15) 1(-1349.14,1348.59) 1(-1349.14,1348.59) 1(-1267.81,1181.64) 1(-1267.81,1181.64) 1(-1267.81,1191.49) 1(-1267.81,1238.73) 1(-1267.81,1248.57) 1(-1267.81,1248.57) 1(-1232.38,1181.64) 1(-1232.38,1181.64) 1(-1232.38,1248.57) 1(-1232.38,1248.57) 1(-1232.38,1191.49) 1(-1232.38,1238.73)
  round 1.5 on Mech16: 1(-474.89,503.61)
  round 2.46 on Mech16: 1(-69.32,1342.99) 1(-59.47,1342.99)
  round 1.48 on Mech16: 1(-59.48,1399.48) 1(-59.48,1399.48) 1(-59.48,1504.6) 1(-59.48,1504.6)
  round 2.5 on Mech16: 1(104.06,1504.6) 1(104.06,1504.6)
  round 102.99 hole 102.99: HOLE1(1228.45,1786.73) HOLE2(1228.45,2736.73) HOLE3(-206.55,2731.73)
  round 127.95 hole 127.95: HOLE4(248.97,637.58) HOLE5(248.97,1383.25)

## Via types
v1: diameter 18, hole 8, Top Layer to Bottom, tented both sides, 729 vias
v2: diameter 19.68, hole 7.87, Top Layer to Bottom, 77 vias
v3: diameter 24, hole 12, Top Layer to Bottom, tented both sides, 52 vias

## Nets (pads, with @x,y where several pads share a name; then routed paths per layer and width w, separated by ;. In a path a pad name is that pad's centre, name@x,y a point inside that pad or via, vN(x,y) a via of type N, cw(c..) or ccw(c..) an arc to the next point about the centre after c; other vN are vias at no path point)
3V3_EMU_HDR: C89.2 J4.1 TP24.1 U13.1
3V3_LDO2: C21.2 C22.1 C23.2 C24.1 C27.2 C28.1 C32.1 C33.1 C34.1 C35.1 C36.1 C37.2 C71.2 C74.2 C109.1 C110.1 C111.1 C112.1 C113.1 C114.1 C115.1 C116.1 C117.1 C118.1 C121.2 EC1.119 J1.28 J5.2 J5.3 J8.10 R5.2 R43.1 R44.1 R60.2 R79.1 R80.1 R86.1 R87.1 R88.1 R91.1 R95.1 R96.1 R99.1 R100.2 R101.2 R102.2 R103.2 R104.2 R105.2 R122.1 R123.1 R124.1 R130.2 R131.2 R133.1 TP2.1 U3.6 U4.6 U5.6 U6.6 U7.6 U8.5 U9.5 U11.1 U16.1 U16.17 U16.30 U17.1 U17.17 U17.30 U18.1 U18.17 U18.30 U19.10 U20.5 | length 4966.9
  Top Layer w8: U3.6@59.32,-268.47 59.32,-249.19 ; 239.67,-286.87 U4.6@239.67,-267.59
  Top Layer w10: v1(47.62,-193.75) C32.1@47.62,-219.5 47.62,-237.5 59.32,-249.19 ; v1(223,-354) 240.2,-336.8 C33.1@240.2,-310.04 240.2,-287.41 ; R122.1@486.93,640.53 487.16,640.76 518.76,640.76 v1(519,641) ; v1(1227.84,1605.69) 1230.01,1605.69 1231.7,1603.99 R103.2@1260.22,1603.99 ; v1@1230.21,1553.49 1230.54,1553.16 1259.89,1553.16 R101.2@1260.22,1553.49 ; v1@1230.86,1510.19 R104.2@1260.22,1510.19 ; U19.10@1575.63,1591.65 1576.56,1591.65 1577.47,1592.55 C118.1@1577.47,1664.99 v1(1577.47,1693) ; R105.2@1715.71,1437.99 1716.64,1437.06 v1(1716.64,1405.18) ; R100.2@1715.71,1494.49 R102.2@1715.71,1552.28 v1(1715.71,1577.71) ; R86.1@1841.54,2386.55 v1(1841.54,2417) ; U9.5@2050.57,2386.55 C71.2@2125,2386.55 v1(2125,2417) ; R124.1@2148.28,2311.75 v1(2176,2311.75) ; v1(2381,1617) 2381.32,1616.69 2408.04,1616.69 R43.1@2408.35,1616.37 ; v1@2587.02,1689.98 C37.2@2625.11,1689.97 2625.62,1689.46 U8.5@2625.62,1616.37 ; R44.1@2689.49,1580.94 v1(2689.49,1604) ; v1(2758.51,2396.67) R88.1@2792.46,2396.67
  Top Layer w12: v1(418,918.99) C121.2@487.49,918.99 ; U20.5@487.49,852.66 C121.2@487.49,918.31 ; C121.2@493.3,920.18 511.28,920.18 518.31,927.21 518.31,959.85 519.77,961.31 561.98,961.31 R123.1@562.29,961.62 ; J1.28@1458.21,444.88 1458.21,490.35 ; v1(1813,2691) R131.2@1850.46,2691 ; v1(2220.02,2691) R130.2@2257.48,2691 ; v1(3170,2711.17) R91.1@3170,2748.63
  Top Layer w18: v1(1438.21,564.07) v1(1438.21,526.36) 1438.21,510.35 1458.21,490.35
  Top Layer w20: EC1.119@1956.16,-528.32 1956.16,-333.01
  Top Layer w22: v1(3290.4,362.4) v1(3290.4,339.84) 3290.4,328.4 C74.2@3341.94,328.4 U11.1@3428.29,328.4
  Top Layer w31.5: 1956.16,-333.01 C28.1@1956.16,-312.16 C27.2@1956.16,-256.16 v3(1956.16,-193) v3(1956.16,-159.78) TP2.1@1956.16,-123.78
  PWR w10: v1(2758.51,2396.67) 2786.09,2396.67 2791.95,2390.81 v1(2791.95,2303.89)
  PWR w16: v1(2381,1617) 2514,1617 ; v1(2587,1690) 2551,1654 2514,1617 ; v1(2791.95,1351.13) 2773.54,1369.54 2773.54,1577.46 2747,1604 v1(2689.49,1604) 2655.49,1570 2561,1570 2514,1617
  Bottom w7.89: 113.79,938.68 J5.3@139.23,938.68 ; J5.2@260.49,922.93 285.93,922.93
  Bottom w8: 334.47,-284.23 U5.6@334.47,-267.59 ; 560.44,-284.23 U6.6@560.44,-267.59 ; 752.72,-284.23 U7.6@752.72,-267.59
  Bottom w10: v1(-18.28,942.62) C21.2@23.23,942.62 27.17,938.68 C22.1@79.23,938.68 113.79,938.68 ; 285.93,922.93 C24.1@320.49,922.93 ; v1(321.39,-389.19) 334.47,-376.11 C36.1@334.47,-309.81 334.47,-284.23 ; v1(530.44,-280.4) C34.1@530.44,-309.7 535.07,-305.07 554.58,-305.07 560.44,-299.21 560.44,-284.23 ; v1(722.72,-280.4) C35.1@722.72,-309.7 727.35,-305.07 746.86,-305.07 752.72,-299.21 752.72,-284.23 ; v1(801.8,1183.7) 825.97,1183.7 C114.1@826.28,1184.02 U17.1@826.28,1108 ; v1(950.4,879.94) C113.1@983.76,879.94 U17.30@983.76,978.08 ; R96.1@964.08,1225.52 964.32,1225.76 990.76,1225.76 v1(991,1226) ; v1@1116.34,1206.14 1116.48,1206 1141.1,1206 C112.1@1141.24,1206.14 U17.17@1141.24,1108 ; v1@1238.18,1206.28 1238.32,1206.14 C117.1@1262.94,1206.14 ; U18.1@1262.94,1108 C117.1@1262.94,1206.14 ; C117.1@1263.09,1206.28 C117.1@1262.94,1206.14 ; v1@1373.89,1248.16 1374.53,1248.8 1400.1,1248.8 R99.1@1400.74,1249.45 ; v1(1383.81,879.94) C115.1@1420.43,879.94 U18.30@1420.43,978.08 ; R80.1@1443.3,2283.91 v1@1470,2283.91 ; R79.1@1445.12,2104.42 v1(1471.82,2104.42) ; v1(1547.3,1210.13) 1573.92,1210.13 C116.1@1577.91,1206.14 U18.17@1577.91,1108 ; v1(1913.03,1043.2) 1915.19,1043.2 1918.85,1046.85 R95.1@1947.94,1046.85 ; v1(1948.78,840.42) 1948.78,869.19 1949.28,869.69 C110.1@1951.88,869.69 U16.1@2050.02,869.69 ; v1(1951.88,1153.39) C111.1@1951.88,1184.65 U16.17@2050.02,1184.65 ; U16.30@2179.94,1027.17 C109.1@2235.06,1027.17 v1(2235.06,1058) ; R133.1@2652.63,279.15 2708.01,279.15 R87.1@2709.63,277.52 2754.82,277.52 2760.68,283.38 v1(2760.68,342.31) ; R5.2@2791.95,1318.07 v1(2791.95,1351.13) ; R60.2@2791.95,2270.82 v1(2791.95,2303.89)
  Bottom w14: C24.1@320.49,922.93 C23.2@376.49,922.93 ; C23.2@376.49,918.99 v1(418,918.99) v1(418,885.99)
  other v1: 1116.2,1206 1238.04,1206.14 1373.89,1249.45 1229.54,1510.19 1229.54,1552.82 1470,2285.52
5V0_LDO3: C29.2 C30.1 EC1.117 J1.34 TP3.1 | length 1483.6
  Top Layer w10: J1.34@1399.15,444.88 v1(1399.15,490)
  Top Layer w20: 1890.21,-360.45 1924.67,-394.91 EC1.117@1924.67,-528.32
  Top Layer w31.5: v3(1879.39,289) 1879.39,113.3 1832.32,66.23 1832.32,-102.17 TP3.1@1889.93,-159.78 ; 1890.21,-360.45 C30.1@1890.21,-312.16 C29.2@1890.21,-256.22 TP3.1@1890.21,-159.78
  PWR w20: v1(1399.15,490) 1431.15,458 1623,458 1763,318 1850.39,318 v3(1879.39,289)
15W_PD: J1.26 R42.2 | length 81.7
  Top Layer w5.66: J1.26@1477.89,444.88 R42.2@1477.89,526.59
1588_SFD: J6.38 TP12.1 | length 201.6
  Bottom w5.66: J6.38@1306.63,2324.89 1480.11,2324.89 TP12.1@1500,2305
AM26x_ADC0_AIN0/DAC_OUT: J1.119 R134.1 | length 263.1
  Top Layer w5.66: R134.1@342.69,-55.76 342.69,-32.19 355.85,-19.03 J1.119@355.85,201.89
AM26x_ADC0_AIN1: J1.117 R135.1 | length 267.5
  Top Layer w5.66: J1.117@375.53,201.89 375.53,160.75 368.89,154.11 368.89,-18.96 384.76,-34.83 384.76,-54.52 R135.1@386,-55.76
AM26x_ADC0_AIN2_P: J1.120 R136.1 | length 635.7
  Top Layer w4: R136.1@256.07,-55.76 256.07,-51.82 272.23,-35.67 272.23,133.74 ccw(c206.29,133.74) 252.91,180.37 233.6,199.68 cw(c277.3,243.38) 233.54,199.75 cw(c277.3,243.38) 215.5,243.38 215.5,343.94 262.56,391 345.58,391 360.19,405.61 360.19,413.07 359.85,413.41 359.85,440.88 J1.120@355.85,444.88
AM26x_ADC0_AIN3_N: J1.118 R137.1 | length 636.2
  Top Layer w4: 263.91,184.93 241.41,207.43 cw(c277.41,243.43) 241.37,207.47 cw(c277.41,243.43) 226.5,243.43 226.5,339.38 267.12,380 350.13,380 371.19,401.05 371.19,413.07 371.53,413.41 371.53,440.88 J1.118@375.53,444.88 ; 263.94,184.9 cw(c217.29,138.3) 283.23,138.3 283.23,-35.67 299.38,-51.82 R137.1@299.38,-55.76
AM26x_ADC0_AIN4_P: J1.115 R138.1 | length 285.1
  Top Layer w4: J1.115@395.22,201.89 399.22,197.89 399.22,170.41 399.56,170.07 399.56,82.44 445.46,36.54 445.46,-35.67 429.3,-51.82 R138.1@429.3,-55.76
AM26x_ADC0_AIN5_N: J1.113 R139.1 | length 285.1
  Top Layer w4: J1.113@414.9,201.89 410.9,197.89 410.9,170.41 410.56,170.07 410.56,87 456.46,41.1 456.46,-35.67 472.61,-51.82 R139.1@472.61,-55.76
AM26x_ADC1_AIN0_P: J1.116 R140.1 | length 778.6
  Top Layer w4: R140.1@212.77,-55.76 212.77,-51.82 196.61,-35.67 196.61,-12.8 cw(c251.07,-12.8) 209.61,22.5 214.59,27.49 ; 214.63,27.52 ccw(c184.64,57.44) 227,57.44 227,129.03 ccw(c186.03,129.03) 215,158 cw(c274.15,217.15) 196.61,185.76 cw(c274.15,217.15) 190.5,217.15 190.5,343.94 cw(c215.5,343.94) 197.77,361.56 cw(c215.5,343.94) 197.82,361.61 210.86,374.66 293.48,457.27 352.21,516 392.24,516 399.56,508.68 399.56,478.75 399.22,478.41 399.22,448.89 J1.116@395.22,444.88
AM26x_ADC1_AIN1_N: J1.114 R141.1 | length 814.6
  Top Layer w4: R141.1@169.46,-55.76 169.46,-51.82 185.61,-35.67 185.61,-12.8 cw(c251.07,-12.8) 201.23,29.63 ; 201.23,29.68 206.79,35.24 ccw(c184.55,57.48) 216,57.48 216,128.98 ccw(c185.92,128.98) 207.22,150.22 cw(c274.04,217.1) 185.61,183.66 cw(c274.04,217.1) 179.5,217.1 179.5,343.94 cw(c215.5,343.94) 189.98,369.32 cw(c215.5,343.94) 190.05,369.39 203.09,382.44 288.93,468.27 341.21,520.56 347.65,527 396.79,527 410.56,513.23 410.56,478.75 410.9,478.41 410.9,448.89 J1.114@414.9,444.88
AM26x_ADC1_AIN2_P: J1.111 R142.1 | length 304.7
  Top Layer w4: J1.111@434.59,201.89 438.59,197.89 438.59,173.34 438.93,173 438.93,112.63 532.07,19.49 532.07,-35.67 515.92,-51.82 R142.1@515.92,-55.76
AM26x_ADC1_AIN3_N: J1.109 R143.1 | length 304.7
  Top Layer w4: J1.109@454.27,201.89 450.27,197.89 450.27,173.34 449.93,173 449.93,117.19 543.07,24.05 543.07,-35.67 559.22,-51.82 R143.1@559.22,-55.76
AM26x_ADC1_AIN4: J1.112 R144.1 | length 664.4
  Top Layer w5.66: J1.112@434.59,444.88 v1@434.59,491.59 ; v1(565,55) 603.87,16.13 R144.1@603.87,-55.76
  Bottom w5.66: v1(435,492) 552.23,374.77 552.23,67.77 v1(565,55)
AM26x_ADC1_AIN5: J1.110 R145.1 | length 723.3
  Top Layer w5.66: J1.110@454,445.15 v1(454,516) ; v1(604,55) 605.12,55 647.18,12.93 R145.1@647.18,-55.76
  Bottom w5.66: v1(454,516) 567.98,402.02 567.98,91.68 604,55.66 v1(604,55)
AM26x_ADC2_AIN0_P: J1.107 R146.1 | length 423.8
  Top Layer w4: J1.107@473.96,201.89 477.96,197.89 477.96,170.41 478.3,170.07 478.3,134.35 520.23,92.42 634.58,92.42 706.64,20.36 706.64,-35.67 R146.1@690.49,-51.82
AM26x_ADC2_AIN1_N: J1.105 R147.1 | length 427.7
  Top Layer w4: J1.105@493.64,201.89 489.64,197.89 489.64,170.41 489.3,170.07 489.3,138.91 524.78,103.42 639.13,103.42 717.64,24.91 717.64,-35.67 733.8,-51.82 R147.1@733.8,-55.76
AM26x_ADC2_AIN2_P: J1.108 R148.1 | length 1227.4
  Top Layer w4: R148.1@126.15,-55.76 126.15,-51.82 110,-35.67 110,29.3 96.23,43.06 1.44,43.06 -83,127.5 -83,235.67 -2.67,316 97.07,316 263.43,482.36 301.89,520.83 336.07,555 458.3,555 478.3,535 478.3,478.75 477.96,478.41 477.96,448.89 J1.108@473.96,444.88
AM26x_ADC2_AIN3_N: J1.106 R149.1 | length 1263.8
  Top Layer w4: R149.1@82.85,-55.76 82.85,-51.82 99,-35.67 99,24.74 91.68,32.06 -3.12,32.06 -87.56,116.5 -94,122.95 -94,240.22 -7.22,327 92.51,327 258.87,493.36 290.89,525.38 331.51,566 462.86,566 489.3,539.56 489.3,478.75 489.64,478.41 489.64,448.89 J1.106@493.64,444.88
AM26x_ADC2_AIN4: J1.103 R150.1 | length 469.8
  Top Layer w5.66: J1.103@513.33,201.89 513.33,159.21 538.69,133.85 653.42,133.85 680.37,106.9 741.31,106.9 777.1,71.11 R150.1@777.1,-55.76
AM26x_ADC2_AIN5: J1.101 R151.1 | length 479.8
  Top Layer w5.66: J1.101@533.01,201.89 533.01,158 544.51,146.51 658.67,146.51 685,120.17 746.83,120.17 820.41,46.59 R151.1@820.41,-55.76
AM26x_ADC_CAL0: J1.92 R152.1 | length 596.9
  Top Layer w5.66: v1(631.44,393.51) J1.92@631.44,444.88 ; v1(863,62.17) 863,-55.04 R152.1@863.72,-55.76
  SIG1 w6.66: v1(631.44,393.51) 631.44,295.56 863,64 v1(863,62.17)
AM26x_EPWM0_A: EC1.49 J1.15 | length 1374.2
  Top Layer w5.66: EC1.49@727.82,-528.32 727.82,-449 774.69,-402.12 774.69,-336.49 v1(878.53,-232.66) ; J1.15@1576.32,201.89 1576.32,75.13 v1(1598.77,52.61) v1(1598.77,52.61)
  Bottom w5.66: v1(878.53,-232.66) 913.67,-197.52 1381.3,-197.52 1598.77,19.95 v1(1598.77,52.61)
AM26x_EPWM0_B: EC1.51 J1.13 | length 1365.4
  Top Layer w5.66: EC1.51@759.31,-528.32 759.31,-445 789.19,-415.12 789.19,-341.57 880.27,-250.49 v1(900.93,-250.49) ; v1@1596,92.08 J1.13@1596,201.89
  Bottom w5.66: v1(900.93,-250.49) 941.23,-210.18 1386.55,-210.18 1616.6,19.88 1616.6,70.09 v1(1596,90.69)
AM26x_EPWM1_A: EC1.53 J1.11 | length 1360.6
  Top Layer w5.66: EC1.53@790.81,-528.32 790.81,-451.58 804,-438.39 804,-345.6 879.86,-269.74 v1(923.98,-269.74) ; J1.11@1615.69,201.89 1615.69,75.1 1635.37,55.42 v1(1635.37,52.09)
  Bottom w5.66: v1(923.98,-269.74) 970.88,-222.84 1391.79,-222.84 1635.37,20.74 v1(1635.37,52.09)
AM26x_EPWM1_B: EC1.55 J1.9 | length 1377.3
  Top Layer w5.66: EC1.55@822.31,-528.32 822.31,-346.94 844.12,-325.12 936.71,-325.12 950.1,-311.73 v1(950.1,-270.54) ; v1@1635.36,90.71 J1.9@1635.36,201.87
  Bottom w5.66: v1(950.1,-270.54) 968.96,-251.68 1380.85,-251.68 1653.2,20.67 1653.2,72.82 v1(1635.34,90.69)
AM26x_EPWM2_A: EC1.50 J1.7 | length 1430.3
  Top Layer w5.66: J1.7@1655.06,201.89 1655.06,75.1 1674.74,55.42 v1(1674.74,52.09)
  Bottom w5.66: EC1.50@727.82,-528.32 727.82,-434.4 784.33,-377.89 784.33,-354.43 849.07,-289.68 958.51,-289.68 983.85,-264.34 1386.1,-264.34 1674.74,24.31 v1(1674.74,52.09)
AM26x_EPWM2_B: EC1.52 J1.5 | length 1423.9
  Top Layer w5.66: v1(1674.74,90.69) J1.5@1674.74,201.89
  Bottom w5.66: EC1.52@759.31,-528.32 759.31,-420.81 796.99,-383.13 796.99,-359.67 854.32,-302.34 963.76,-302.34 989.1,-277 1391.34,-277 1692.57,24.23 1692.57,72.86 v1(1674.74,90.69)
AM26x_EPWM3_A: EC1.54 J1.3 | length 1422
  Top Layer w5.66: J1.3@1694.43,201.89 1692.68,200.14 1692.68,73.45 v1(1714.11,52.01)
  Bottom w5.66: EC1.54@790.81,-528.32 790.81,-407.21 809.65,-388.38 809.65,-364.91 859.56,-315 969,-315 994.34,-289.66 1396.58,-289.66 1714.11,27.87 v1(1714.11,52.01)
AM26x_EPWM3_B: EC1.56 J1.1 | length 1417.1
  Top Layer w5.66: v1(1710.51,90.27) 1710.51,93.6 1714.11,97.21 J1.1@1714.11,201.89
  Bottom w5.66: EC1.56@822.31,-528.32 822.31,-370.16 864.46,-328 973.91,-328 999.58,-302.32 1401.83,-302.32 1731.94,27.79 1731.94,68.83 v1(1710.51,90.27)
AM26x_EPWM4_A: EC1.57 J1.16 | length 2079.8
  Top Layer w5.66: EC1.57@979.79,-528.32 979.79,-116.21 998.62,-97.38 998.62,-43.7 950.85,4.08 950.85,234.85 v1(992,276) ; v1(992,578) 1035.15,534.85 1121.04,534.85 1260.42,674.23 1573.63,674.23 1625.98,621.87 1625.98,527.7 1579.49,481.21 1579.49,448.06 J1.16@1576.32,444.88
  Bottom w5.66: v1(992,276) v1(992,578)
AM26x_EPWM4_B: EC1.59 J1.14 | length 2059.7
  Top Layer w5.66: EC1.59@1011.28,-528.32 1011.28,-38.45 963.51,9.32 963.51,214.51 v1(1026,277) ; v1@1025.9,578 v1@1025.95,577.95 ; v1(1026,578) 1056.49,547.51 1115.8,547.51 1255.18,686.89 1578.87,686.89 1638.64,627.12 1638.64,522.46 1596,479.82 J1.14@1596,444.88
  Bottom w5.66: v1(1026,277) v1(1026,578)
AM26x_EPWM5_A: EC1.61 J1.12 | length 2055.7
  Top Layer w5.66: EC1.61@1042.78,-528.32 1042.78,-52.05 976.17,14.57 976.17,193.17 v1(1059,276) ; v1(1059,578) 1076.83,560.17 1110.55,560.17 1249.93,699.55 1584.12,699.55 1651.3,632.36 1651.3,517.21 1615.69,481.6 J1.12@1615.69,444.88
  Bottom w5.66: v1(1059,276) v1(1059,578)
AM26x_EPWM5_B: EC1.63 J1.10 | length 2049.2
  Top Layer w5.66: EC1.63@1074.27,-528.32 1074.27,-65.64 988.83,19.81 988.83,175.7 1089.12,276 v1(1090,276) ; v1(1090,578) 1224.21,712.21 1589.36,712.21 1663.96,637.6 1663.96,509.62 1635.37,481.03 J1.10@1635.37,444.88
  Bottom w5.66: v1(1090,276) v1(1090,578)
AM26x_EPWM6_A: EC1.58 J1.8 | length 1666.6
  Top Layer w5.66: v1(1606.81,390.76) 1642.3,390.76 1653.38,401.85 1653.38,443.2 J1.8@1655.06,444.88
  Bottom w5.66: EC1.58@979.79,-528.32 979.79,-345.21 1010.02,-314.98 1407.07,-314.98 1718.21,-3.84 1759.21,-3.84 1771.31,8.26 1771.31,84.97 1628.16,228.13 1628.16,297.42 1606.84,318.74 v1(1606.81,390.76)
AM26x_EPWM6_B: EC1.60 J1.6 | length 1569.7
  Top Layer w5.66: v1(1625.67,370.26) 1628.02,372.61 1642.05,372.61 1673.2,403.77 1673.2,443.34 J1.6@1674.74,444.88
  Bottom w5.66: EC1.60@1011.28,-528.32 1011.28,-460.87 1144.51,-327.64 1412.32,-327.64 1723.46,-16.5 1764.45,-16.5 1783.97,3.02 1783.97,90.22 1640.82,233.37 1640.82,302.66 1623.96,319.52 1623.96,368.55 v1(1625.67,370.26)
AM26x_EPWM7_A: EC1.62 J1.4 R31.2 | length 3356.4
  Top Layer w5.66: v1(405.92,1056.21) 659.43,1056.21 990.77,724.87 1601.18,724.87 1676.62,649.42 1676.62,503.38 1694.43,485.57 J1.4@1694.43,444.88 1694.43,400.18 v1(1646.23,351.98)
  Bottom w5.66: R31.2@380.28,984.18 381,984.91 381,1031.29 v1(405.92,1056.21) ; EC1.62@1042.78,-528.32 1042.78,-447.28 1149.76,-340.3 1502.7,-340.3 1547.59,-295.41 1629.88,-295.41 1660.16,-265.13 1660.16,-158.99 1670.49,-148.65 1670.49,-148.49 1796.63,-22.35 1796.63,95.46 1656.12,235.98 1656.12,314.79 1646.23,324.68 v1(1646.23,351.98)
AM26x_EPWM7_B: EC1.64 J1.2 | length 1598.4
  Top Layer w5.66: v1(1678.66,351.98) 1714.11,387.43 J1.2@1714.11,444.88
  Bottom w5.66: EC1.64@1074.27,-528.32 1074.27,-433.69 1155,-352.96 1507.94,-352.96 1552.84,-308.07 1635.12,-308.07 1672.82,-270.37 1672.82,-164.23 1809.29,-27.76 1809.29,100.71 1678.66,231.34 v1@1678.66,348.96
AM26x_EPWM8_A: EC2.159 J2.58 | length 5583.7
  Top Layer w5.66: v1(-306,167) -272,167 -105,334 -105,1248.64 -122.7,1266.34 J2.58@-171.52,1266.34 ; v1(3332.7,-370.43) 3376.32,-370.43 3384.12,-378.23 3384.12,-517.91 EC2.159@3379.06,-522.97
  SIG1 w6.66: v1(-306,167) -175.34,36.34 469.34,36.34 616.07,-110.39 868.97,-110.39 1084.21,-325.63 1955.37,-325.63 2049.62,-231.38 2049.62,-116.02 2075,-90.64 2761.21,-90.64 3040.99,-370.43 v1(3332.7,-370.43)
AM26x_EPWM8_B: EC2.161 J2.60 | length 5489.4
  Top Layer w5.66: v1(-281.35,196) -281.35,238.23 -119,400.58 -119,1238.86 -126.8,1246.65 J2.60@-171.52,1246.65 ; v1(3359,-351.63) 3394.71,-351.63 3410.55,-367.47 EC2.161@3410.55,-522.97
  SIG1 w6.66: v1(-281.35,196) -135.35,50 475,50 621.73,-96.73 874.63,-96.73 1089.87,-311.97 1914.03,-311.97 1995.61,-230.39 1995.61,-148.29 2066.92,-76.98 2766.87,-76.98 3041.51,-351.63 v1(3359,-351.63)
AM26x_EPWM9_A: EC2.163 J2.54 | length 5199.1
  Top Layer w5.66: v1(-223.39,1178) -241.23,1195.84 -241.23,1286.73 -222.95,1305.02 -172.21,1305.02 J2.54@-171.52,1305.71 ; v1(3332.7,-332.83) 3415.63,-332.83 3442.05,-359.24 EC2.163@3442.05,-522.97
  SIG1 w6.66: v1(-223.39,1178) -225.56,1175.83 -238.44,1175.83 -296.36,1117.91 -296.36,891.69 526.11,69.22 526.11,34.05 555.59,4.57 640.59,4.57 728.23,-83.07 880.29,-83.07 1095.33,-298.11 1904.89,-298.11 1981.95,-221.05 1981.95,-142.63 2061.27,-63.32 2772.52,-63.32 3042.03,-332.83 v1(3332.7,-332.83)
AM26x_EPWM9_B: EC2.165 J2.56 | length 5178.4
  Top Layer w5.66: v1(-223.39,1210) -223.39,1273.55 -210.92,1286.02 J2.56@-171.52,1286.02 ; v1(3359,-314.03) 3440.17,-314.03 3473.54,-347.41 EC2.165@3473.54,-522.97
  SIG1 w6.66: v1(-223.39,1210) -205.06,1191.67 -205.06,1170.41 -215.81,1159.66 -235.29,1159.66 -282.7,1112.25 -282.7,897.35 540.41,74.24 540.41,39.07 561.25,18.23 647.38,18.23 735.01,-69.41 885.95,-69.41 1100.99,-284.45 1847.07,-284.45 1913.35,-218.16 1913.35,-164.44 2028.13,-49.66 2778.18,-49.66 3042.55,-314.03 v1(3359,-314.03)
AM26x_EQEP0_A: EC1.100 J1.71 | length 2004.5
  Top Layer w5.66: J1.71@828.29,201.89 828.29,269.68 v1(847.97,289.36)
  SIG1 w6.66: v1(847.97,289.36) 828.68,270.07 828.68,156.94 910.16,75.46 971.28,75.46 1099.44,-52.71 1166.71,-52.71 1303.34,-189.34 1793.05,-189.34 v1(1880.64,-101.74)
  Bottom w5.66: EC1.100@1641.2,-528.32 1641.2,-462.47 1793.73,-309.94 1793.73,-169.82 1849.39,-114.15 1868.23,-114.15 v1(1880.64,-101.74)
